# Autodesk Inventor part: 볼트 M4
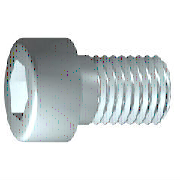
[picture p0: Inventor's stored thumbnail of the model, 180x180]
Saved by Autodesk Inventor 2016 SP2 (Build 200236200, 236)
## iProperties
IsCustomPart: 0
Created: 2012-02
Part Number: 볼트 M4
Material: 스테인리스강
Description: 6각 소켓 머리 캡 나사
Document SubType Name: Modeling
Standard: ISO 4762
Designer: mduedu
Standard Revision: Fourth edition 2004-03-01
Standards Organization: ISO
Language: ko-KR
Size Designation: M4 x 10
Categories: <MemberInstance><Categories><Category DisplayName="조임쇠" InternalName="e4da775c-781d-43d5-af7c-5136215cf5a6" Mnemonic="FSTN"><Category DisplayName="볼트" InternalN
Density: 7.75 g/cm^3
Appearance: 반광택
Author: mduedu
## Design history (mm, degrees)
sketch "스케치1"
  geometry: L1 (-1, 0)-(10, 0); L2 (10, 0)-(10, 2); L3 (10, 2)-(1.75, 2); L4 (1.75, 2)-(1.32, 2); L5 (1.32, 2)-(0, 2); L6 (0, 2)-(0, 3.5); L7 (0, 3.5)-(-4, 3.5); L8 (-4, 3.5)-(-4, 1.732); L9 (-4, 1.732)-(-2, 1.732); L10 (-2, 1.732)-(-1, 0); L11 (-6.8, 0)-(12.8, 0) reference; L12 (0, -0.7)-(0, 4.2) reference; L13 (1.75, 2)-(0, 2)
  constraints: 22 end point, 6 parallel, 2 collinear, 2 perpendicular, 1 horizontal, 1 point on line
  dimensions: "d1" = 8.25 distance from line of L3.end L2 (= GEL); "d2" = 0.42952 distance of L4.end L3.end (computed from GAL); "d3" = 4 distance between parallel lines of L8 L6 (= KOH); "d4" = 2 distance of L8.end L9.end (= INTI); "d5" = 60 deg angle of L10 L1; "d6" = 4 diameter of L3 L1 (= GD); "d7" = 4 diameter of L5 L1 (= BDM); "d8" = 3.4641 diameter of L9 L1 (= 1.1547 x SW); "d9" = 7 diameter of L7 L1 (= KOD); "d26" = 10 distance between parallel lines of L12 L2 (= NLG)
revolve "본체" sketch "스케치1" stored, may be unused: angle "d10" = 90 deg
sketch "스케치2"
  geometry: L1 (0, -4.9)-(0, 4.9) reference; L2 (-4.9, 0)-(4.9, 0) reference; L3 (1.732, 0)-(0.866, -1.5); L4 (0.866, -1.5)-(-0.866, -1.5); L5 (-0.866, -1.5)-(-1.732, 0); L6 (-1.732, 0)-(-0.866, 1.5); L7 (-0.866, 1.5)-(0.866, 1.5); L8 (0.866, 1.5)-(1.732, 0); 2 further points
  constraints: 12 end point, 1 coincident, 1 horizontal alignment, 1 point on line, 12 other
extrude "슬롯" join sketch "스케치2" stored distance "d11" = 10; taper "d12" = 0 deg
workplane "Work Plane1"
fillet "Fillet2" dims "d30" = 0.1 (= R)
body "Solid1"
fillet "모깎기1" dims "d17" = 0.4 (= RR)
feature "스레드" dims "d13" = 8.25 (= GEL), "d14" = 0
chamfer "모따기1" distance "d15" = 0.42941 (= -0.5 x SPD + 0.5 x GD); stored, may be unused: second distance "d16" = 0.42941 (= GUL), angle "d27" = 45 deg
other parameters: "GD" = 4 [user parameter; used in 2 equation terms], "NLG" = 10 [user parameter; used in 1 equation term], "GEL" = 8.25 [user parameter; used in 2 equation terms], "KOD" = 7 [user parameter; used in 1 equation term], "KOH" = 4 [user parameter; used in 1 equation term], "INTI" = 2 [user parameter; used in 1 equation term], "GAL" = 0.42941 (= 0.61345 x PTC) [user parameter; used in 1 equation term], "GUL" = 0.42941 (= 0.61345 x PTC) [user parameter; used in 1 equation term], "BDM" = 4 (= NND) [user parameter; used in 1 equation term], "SW" = 3 [user parameter; used in 2 equation terms], "RR" = 0.4 [user parameter; used in 1 equation term], "SPD" = 3.14117 (= NND - 1.2269 x PTC) [user parameter; used in 1 equation term], "d19" = 0, "d28" = 0, "d29" = 0, "R" = 0.1 [user parameter; used in 1 equation term], "TOA" = 30 deg [user parameter], "GD1" = 3.14117 (= THREADDIA - 1.2269 x PTC) [user parameter], "THREADDIA" = 4 [user parameter; used in 1 equation term], "FAWI" = 45 deg [user parameter], "TPU" = 14.28571 (computed from PTC) [user parameter], "PTC" = 0.7 [user parameter; used in 5 equation terms], "NND" = 4 [user parameter; used in 2 equation terms], "E0" = 3.465 (= 1.155 x SW) [user parameter]
